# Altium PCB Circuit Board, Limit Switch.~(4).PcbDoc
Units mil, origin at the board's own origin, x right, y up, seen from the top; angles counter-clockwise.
Board outline 1122.99 x 1124 mil, 2 copper layers (Top Layer, Bottom Layer); 0 components, 2 nets, 8 pads, 0 vias.
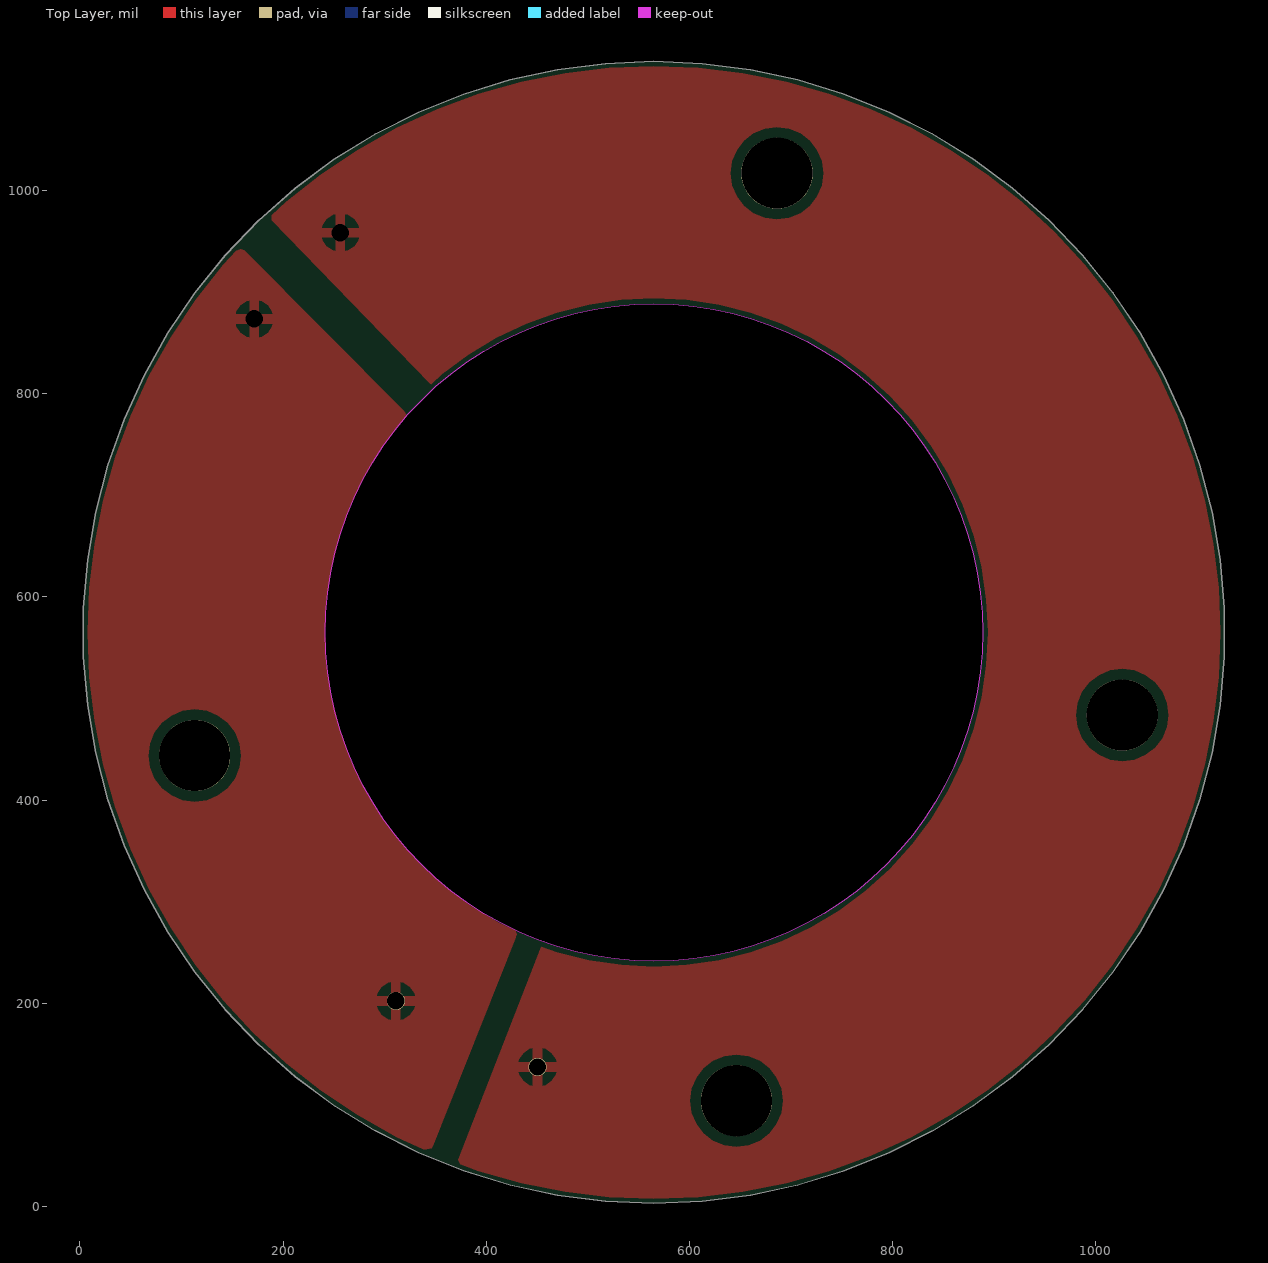
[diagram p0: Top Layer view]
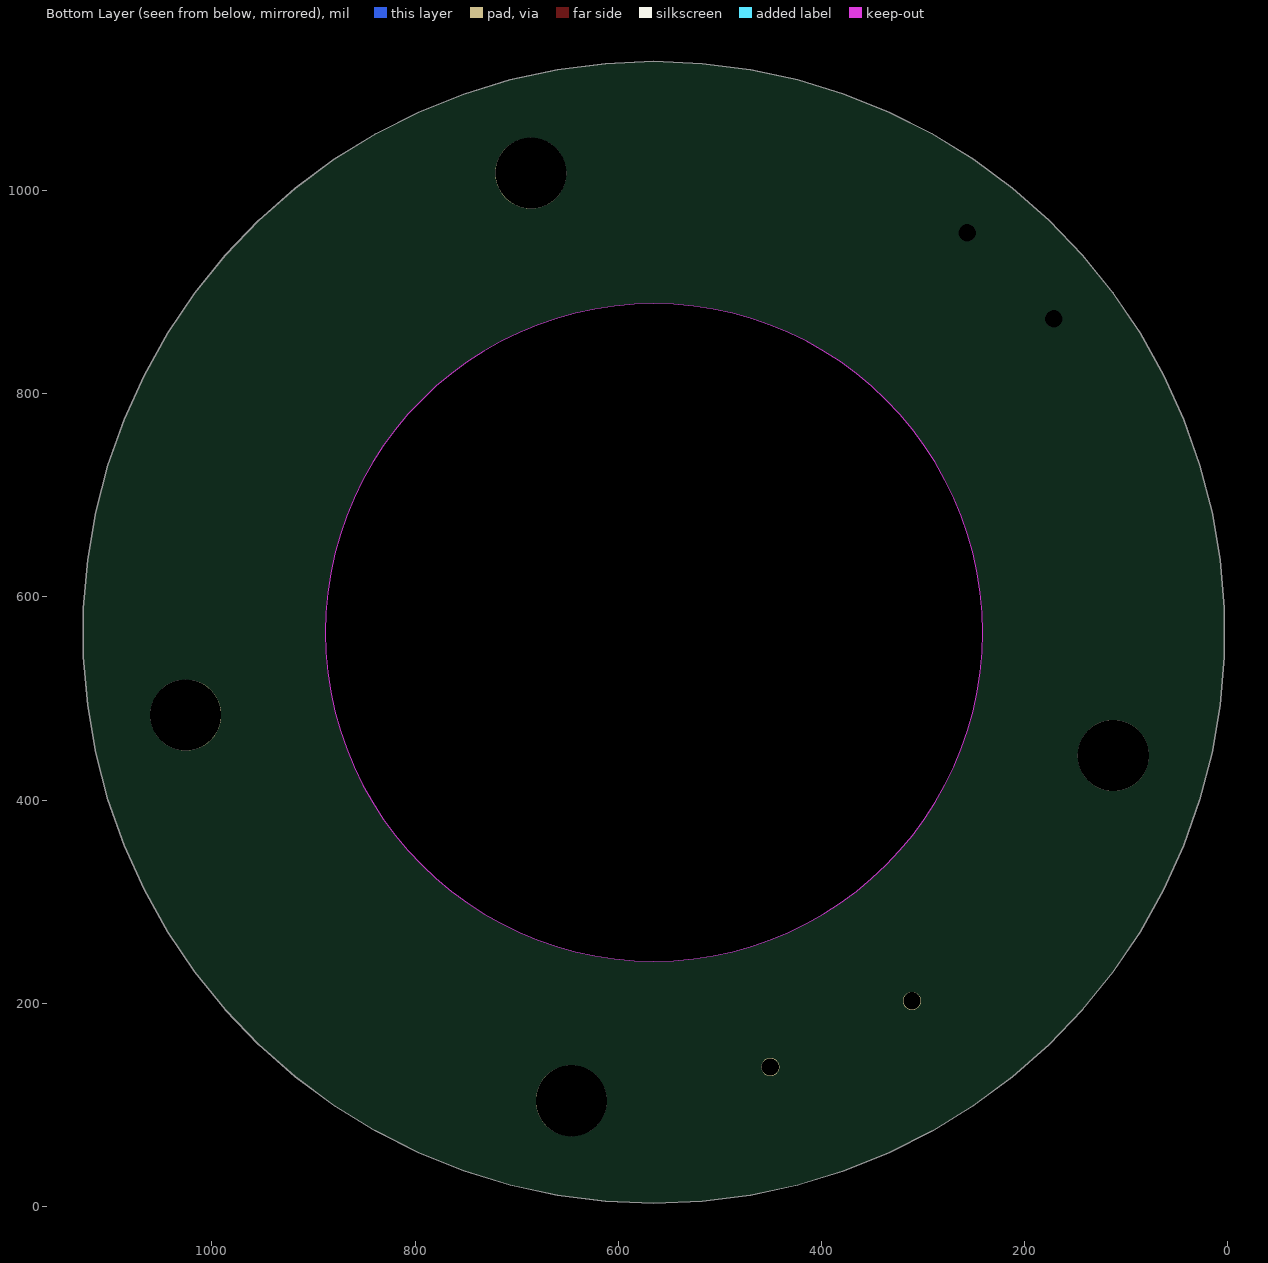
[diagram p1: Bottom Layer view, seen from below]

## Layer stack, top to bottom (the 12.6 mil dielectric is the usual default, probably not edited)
Top Layer: signal copper 1.4
Dielectric: dielectric 12.6, FR-4, Dk 4.8
Bottom Layer: signal copper 1.4

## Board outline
565,1127 517.34,1124.98 470.02,1118.92 423.39,1108.87 377.78,1094.9 333.51,1077.11 290.92,1055.63 250.29,1030.62 211.94,1002.26 176.13,970.74 143.12,936.3 113.15,899.18 86.44,859.66 63.18,818.01 43.53,774.55 27.63,729.57 15.61,683.4 7.55,636.38 3.51,588.85 3.51,541.15 7.55,493.62 15.61,446.6 27.63,400.43 43.53,355.45 63.18,311.99 86.44,270.34 113.15,230.82 143.12,193.7 176.13,159.26 211.94,127.74 250.29,99.38 290.92,74.37 333.51,52.89 377.78,35.1 423.39,21.13 470.02,11.08 517.34,5.02 565,3 612.66,5.02 659.98,11.08 706.61,21.13 752.22,35.1 796.49,52.89 839.08,74.37 879.71,99.38 918.06,127.74 953.87,159.26 986.88,193.7 1016.85,230.82 1043.56,270.34 1066.82,311.99 1086.47,355.45 1102.37,400.43 1114.39,446.6 1122.45,493.62 1126.49,541.15 1126.49,588.85 1122.45,636.38 1114.39,683.4 1102.37,729.57 1086.47,774.55 1066.82,818.01 1043.56,859.66 1016.85,899.18 986.88,936.3 953.87,970.74 918.06,1002.26 879.71,1030.62 839.08,1055.63 796.49,1077.11 752.22,1094.9 706.61,1108.87 659.98,1118.92 612.66,1124.98
cut-out: 565,241.5 cw(c565,565) 241.5,565 cw(c565,565) 565,888.5 cw(c565,565) 888.5,565 cw(c565,565)

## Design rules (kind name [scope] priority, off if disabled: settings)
Clearance [All] p1: gap=10
PolygonConnect [All] p1: connectstyle=Relief reliefconductorwidth=10 reliefentries=4 polygonreliefangle="90 Angle"
RoutingVias [All] p1: holewidth=28 width=50 viastyle="Through Hole" minholewidth=28 minwidth=50 maxholewidth=28 maxwidth=50
SilkscreenOverComponentPads [All] p1: minsilkscreentomaskgap=10
SolderMaskExpansion [All] p1: expansion=4
Width [All] p1: maxlimit=10 minlimit=10 preferedwidth=10
27 further rules are at their usual default settings.

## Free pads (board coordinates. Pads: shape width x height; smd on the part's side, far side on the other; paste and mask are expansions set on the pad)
  round 70 hole 70 unplated: 1(112.95,443.87)
  round 16.1 hole 17.1: 1(171.57,873.57) 1(256.43,958.42)
  round 18 hole 17.1: 1(311.05,202.32) 1(450.41,137.34)
  round 70 hole 70: 1(646.27,104.11) 1(686.13,1017.05) 1(1025.89,483.73)

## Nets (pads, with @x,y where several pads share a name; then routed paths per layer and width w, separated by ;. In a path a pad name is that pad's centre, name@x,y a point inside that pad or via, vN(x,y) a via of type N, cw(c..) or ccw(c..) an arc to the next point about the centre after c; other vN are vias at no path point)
SW1: pad.1@171.57,873.57 pad.1@311.05,202.32
SW2: pad.1@256.43,958.42 pad.1@450.41,137.34
copper on no net: | length 563.6
  Top Layer w10: 300.43,5842.16 ccw(c565,5656) 426.69,5363.56

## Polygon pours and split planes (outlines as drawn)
SW2 on Top Layer "Top Layer-No Net" (solid, pour order 19): 371.06,42.85 ccw(c565,565) 186.32,973.48 186.75,972.73 345,810 345.61,809.5 cw(c565,565) 454.32,255.71 454.2,255.75
SW1 on Top Layer "Top Layer-No Net" (solid, pour order 15): 318.91,774.96 ccw(c315.98,779.02) 320.99,779.02 ccw(c315.98,779.02) 320.84,780.23 ccw(c315.94,779.19) 318.74,783.35 161.25,940.84 ccw(c157.7,937.3) 157.97,942.31 ccw(c157.46,937.32) 153.76,940.7 ccw(c565,565) 337.86,56.4 ccw(c339.9,60.98) 341.25,56.15 ccw(c342.4,61.03) 347.06,59.18 428.51,263.6 ccw(c423.86,265.46) 428.87,265.46 ccw(c423.86,265.46) 428.87,265.49 ccw(c424.55,268.04) 429.57,268.04 ccw(c424.55,268.04) 426.69,272.57 cw(c565,565)

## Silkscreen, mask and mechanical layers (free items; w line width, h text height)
Mechanical 1:
  circle w10: c565,565 r562
  circle w10: c565,565 r323.5
  lines w10: 157.46,937.32 ccw(c565,565) 339.9,60.98 ; 157.7,937.3 315.98,779.02 ; 186.32,973.48 cw(c565,565) 371.06,42.85 ; 186.75,972.73 345,810 ; 315.94,779.19 ccw(c565,565) 424.55,268.04 ; 342.4,61.03 423.86,265.46 ; 345.61,809.5 cw(c565,565) 454.32,255.71 ; 371.11,42.84 454.2,255.75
